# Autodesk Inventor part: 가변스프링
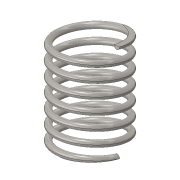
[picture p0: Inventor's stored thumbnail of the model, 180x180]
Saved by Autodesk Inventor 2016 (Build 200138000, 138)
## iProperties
Created: 2020-01
Part Number: 가변스프링
Material: 스테인레스 스틸
Document SubType Name: Modeling
Designer: user
Mass: 10.8825 g
Surface Area: 27.5643 cm^2
Volume: 1.36032 cm^3
Density: 8 g/cm^3
Appearance: 반연마
Author: user
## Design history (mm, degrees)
sketch "스케치1"
  geometry: L1 (0, 0)-(10, 0); L2 (10, 0)-(10, 28.7); L3 (10, 28.7)-(0, 28.7); L4 (0, 28.7)-(0, 0); C1 r 1 at (10, 0)
  constraints: 8 end point, 2 parallel, 1 centre point, 1 coincident, 1 horizontal, 1 perpendicular
  dimensions: "d0" = 2 diameter of C1; "d1" = 28.7 distance of L1.end L2.end (derived); "d2" = 20 diameter of L2 L4
feature "코일1" sketch "스케치1" pitch "d3" = 10; turns "d5" = 7; dims "d4" = 28.7 (= d1), "d6" = 0, angle "d7" = 90 deg, angle "d8" = 90 deg, "d9" = 0, "d10" = 0
sketch "스케치2"
  geometry: L1 (-9, 0)-(-11, 0) reference; 1 further point
  constraints: 1 horizontal alignment
extrude "돌출1" cut sketch "스케치2" stored distance "d11" = 10; taper "d12" = 0 deg
node "작업 평면1"
sketch "스케치3"
  geometry: L1 (-1, 0)-(1, 0) reference; 1 further point
  constraints: 1 horizontal alignment
extrude "돌출2" cut sketch "스케치3" stored distance "d14" = 10; taper "d15" = 0 deg
node "솔리드1"
node "절단 모서리 투영1"
node "절단 모서리 투영2"
other parameters: "d13" = 90 deg
